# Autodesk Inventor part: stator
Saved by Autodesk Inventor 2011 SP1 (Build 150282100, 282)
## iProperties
Created: 2010-12
Part Number: stator
Document SubType Name: Modeling
Designer: eric
Density: 1 g/cm^3
Author: eric
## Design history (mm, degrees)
feature "Base1"
node "Solide1"
node "Corps solides"
node "Corps surfaciques"
